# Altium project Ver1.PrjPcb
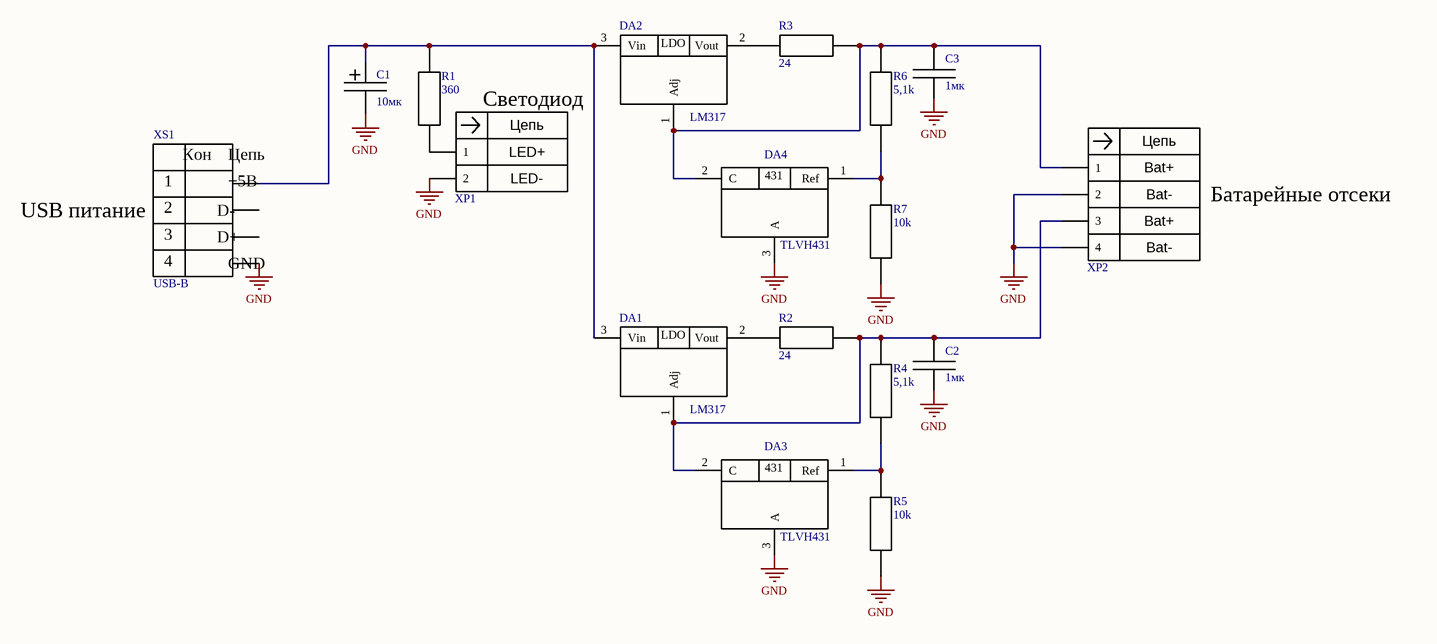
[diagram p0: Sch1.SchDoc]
1 sheet, 17 parts. Net scope: global (net labels, ports and power ports of the same name join across sheets).
Board file: PCB1.PcbDoc

## Sheet Sch1.SchDoc: Наименование
size 420 x 297 mm; ApprovedBy: Утвердил; CheckedBy: Проверил; Author: Разработал; CompanyName: Организация; DocumentNumber: Обозначение; SheetNumber: Лист; SheetTotal: Листов; TechContr: Техн.контр.; NormCotr: Нормоконтроль; DocumentType: Тип документа; InvNumOrigin: Инв № подл; InvNumDuplicate: Инв № дубл; InsteadOfInvNum: Взам. инв. №; RefNumber: Справ. №; InitialUsage: Перв. примен.; Lit: О; PageSetup: Record=PageOptions|CenterHorizontal=True|CenterVertical=True|PrintScale=0.70|XCorrection=1.00|YCorrection=1.00|PrintKind=2|BorderSize=5000000|LeftOffset=0|BottomOffset=0|Orientation=2|PaperLength=1000|PaperWidth=1000|Scale=100|PaperSource=7|PrintQuality=-4|MediaType=1|DitherType=10|PaperKind=A4|PrintScaleMode=1

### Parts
C1  value 10мк  [Type B]  (hidden comment: Type B)
C2  value 1мк  [RC_1206]  (hidden comment: C_1206)
C3  value 1мк  [RC_1206]  (hidden comment: C_1206)
DA1  LM317  [SOT-223]
DA2  LM317  [SOT-223]
DA3  TLVH431  [SOT-23]
DA4  TLVH431  [SOT-23]
R1  value 360  [RC_1206]  (hidden comment: R_1206)
R2  value 24  [RC_1206]  (hidden comment: R_1206)
R3  value 24  [RC_1206]  (hidden comment: R_1206)
R4  value 5,1k  [RC_1206]  (hidden comment: R_1206)
R5  value 10k  [RC_1206]  (hidden comment: R_1206)
R6  value 5,1k  [RC_1206]  (hidden comment: R_1206)
R7  value 10k  [RC_1206]  (hidden comment: R_1206)
XP1  LED  [PLS-2]  (value not drawn)
XP2  Bat  [PLS-4]  (value not drawn)
XS1  USB-B  [USB-B]

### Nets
GND: C1.2 C2.2 C3.2 DA3.3(A) DA4.3(A) R5.1 R7.1 XP1.2 XP2.2 XP2.4 XS1.4
NetC1_1: C1.1 DA1.3(Vin) DA2.3(Vin) R1.2 XS1.1
NetC2_1: C2.1 DA1.1(Adj) DA3.2(C) R2.2 R4.2 XP2.3
NetC3_1: C3.1 DA2.1(Adj) DA4.2(C) R3.2 R6.2 XP2.1
NetDA1_2: DA1.2(Vout) R2.1
NetDA2_2: DA2.2(Vout) R3.1
NetDA3_1: DA3.1(Ref) R4.1 R5.2
NetDA4_1: DA4.1(Ref) R6.1 R7.2
NetR1_1: R1.1 XP1.1

Not connected (* = marked no-connect by the designer): XS1 2 3

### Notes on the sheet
- Светодиод
- USB питание
- Батарейные отсеки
